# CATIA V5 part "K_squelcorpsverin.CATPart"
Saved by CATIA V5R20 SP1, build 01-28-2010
Part number: squelcorpsverin
Publications: "diamverin", "longcorpsverin"
Bounding box of the stored display mesh (mm): x 0 to 205, y -10 to 10, z -10 to 10
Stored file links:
  G:\Khaled_CFAO_2011\SIL\SIL_GR2\zthiebault\Khaled\CAD_ThinkMOTION\K_squelcorpsverin.CATPart
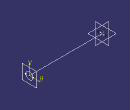
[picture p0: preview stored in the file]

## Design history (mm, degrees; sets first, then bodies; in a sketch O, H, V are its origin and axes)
Parameters
  diamverin = 20 mm {= 20mm}
  longcorpsverin = 205 mm
Set1
  Point1: (0, 0, 0)
  Line1: type Normal, RefPoint Point1, RefSkin yz-plane, Start 0, End 205 {= longcorpsverin}
  Line2: type Normal, RefPoint Point1, RefSkin zx-plane, Start -10, End 10
  Plane1: type OffsetPt, RefPlane yz-plane, RefPoint vertex of Line1
  Sketch1 on Plane1, origin (205, 0, 0), H (0, 1, 0), V (0, 0, 1)
    circle A1 centre (0, 0) radius 10
    point P1 (0, 0)
    radius A1 = 10 {= diamverin /2}
    coincidence: P1 O
Body1 (main body)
